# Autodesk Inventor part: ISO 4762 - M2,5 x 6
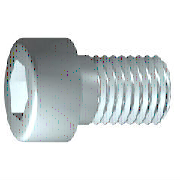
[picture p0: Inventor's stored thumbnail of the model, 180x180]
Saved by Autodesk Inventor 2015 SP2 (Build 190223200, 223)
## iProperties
Created: 2014-02
Part Number: ISO 4762 - M2,5 x 6
Material: Edelstahl, 440C
Description: Innensechskantschraube
Document SubType Name: Modeling
Standard: ISO 4762
Designer: ryll
Standard Revision: 1998
Standards Organization: DIN
Language: de-DE
Size Designation: M2,5 x 6
Categories: <MemberInstance><Categories><Category DisplayName="Verbindungselemente" InternalName="e4da775c-781d-43d5-af7c-5136215cf5a6" Mnemonic="FSTN"><Category DisplayNam
Density: 7.75 g/cm^3
Appearance: Halbpoliert
IsCustomPart: 0
Author: ryll
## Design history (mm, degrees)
sketch "Skizze1"
  geometry: L1 (-0.733, 0)-(6, 0); L2 (6, 0)-(6, 1.25); L3 (6, 1.25)-(1.125, 1.25); L4 (1.125, 1.25)-(0.849, 1.25); L5 (0.849, 1.25)-(0, 1.25); L6 (0, 1.25)-(0, 2.25); L7 (0, 2.25)-(-2.5, 2.25); L8 (-2.5, 2.25)-(-2.5, 1.155); L9 (-2.5, 1.155)-(-1.4, 1.155); L10 (-1.4, 1.155)-(-0.733, 0); L11 (-4.2, 0)-(7.7, 0) reference; L12 (0, -0.45)-(0, 2.7) reference; L13 (1.125, 1.25)-(0, 1.25)
  constraints: 22 end point, 6 parallel, 2 collinear, 2 perpendicular, 1 horizontal, 1 point on line
  dimensions: "d1" = 4.875 distance from line of L3.end L2 (= GEL); "d2" = 0.27615 distance of L4.end L3.end (computed from GAL); "d3" = 2.5 distance between parallel lines of L8 L6 (= KOH); "d4" = 1.1 distance of L8.end L9.end (= INTI); "d5" = 60 deg angle of L10 L1; "d6" = 2.5 diameter of L3 L1 (= GD); "d7" = 2.5 diameter of L5 L1 (= BDM); "d8" = 2.3094 diameter of L9 L1 (= 1.1547 x SW); "d9" = 4.5 diameter of L7 L1 (= KOD); "d26" = 6 distance between parallel lines of L12 L2 (= NLG)
revolve "Körper" sketch "Skizze1" stored, may be unused: angle "d10" = 90 deg
sketch "Skizze2"
  geometry: L1 (0, -3.15)-(0, 3.15) reference; L2 (-3.15, 0)-(3.15, 0) reference; L3 (1.155, 0)-(0.577, -1); L4 (0.577, -1)-(-0.577, -1); L5 (-0.577, -1)-(-1.155, 0); L6 (-1.155, 0)-(-0.577, 1); L7 (-0.577, 1)-(0.577, 1); L8 (0.577, 1)-(1.155, 0); 2 further points
  constraints: 12 end point, 1 coincident, 1 horizontal alignment, 1 point on line, 12 other
extrude "Loch" join sketch "Skizze2" stored distance "d11" = 10; taper "d12" = 0 deg
workplane "Work Plane1"
fillet "Fillet2" dims "d30" = 0.1 (= R)
body "Solid1"
fillet "Rundung1" dims "d17" = 0.25 (= RR)
feature "Gewinde" dims "d13" = 4.875 (= GEL), "d14" = 0
chamfer "Fase1" distance "d15" = 0.27605 (= -0.5 x SPD + 0.5 x GD); stored, may be unused: second distance "d16" = 0.27605 (= GUL), angle "d27" = 45 deg
other parameters: "GD" = 2.5 [user parameter; used in 2 equation terms], "NLG" = 6 [user parameter; used in 1 equation term], "GEL" = 4.875 [user parameter; used in 2 equation terms], "KOD" = 4.5 [user parameter; used in 1 equation term], "KOH" = 2.5 [user parameter; used in 1 equation term], "INTI" = 1.1 [user parameter; used in 1 equation term], "GAL" = 0.27605 (= 0.61345 x PTC) [user parameter; used in 1 equation term], "GUL" = 0.27605 (= 0.61345 x PTC) [user parameter; used in 1 equation term], "BDM" = 2.5 (= NND) [user parameter; used in 1 equation term], "SW" = 2 [user parameter; used in 2 equation terms], "RR" = 0.25 [user parameter; used in 1 equation term], "SPD" = 1.94789 (= NND - 1.2269 x PTC) [user parameter; used in 1 equation term], "d19" = 0, "d28" = 0, "d29" = 0, "R" = 0.1 [user parameter; used in 1 equation term], "TOA" = 30 deg [user parameter], "GD1" = 1.94789 (= THREADDIA - 1.2269 x PTC) [user parameter], "THREADDIA" = 2.5 [user parameter; used in 1 equation term], "FAWI" = 45 deg [user parameter], "TPU" = 22.22222 (computed from PTC) [user parameter], "PTC" = 0.45 [user parameter; used in 5 equation terms], "NND" = 2.5 [user parameter; used in 2 equation terms], "E0" = 2.31 (= 1.155 x SW) [user parameter]
